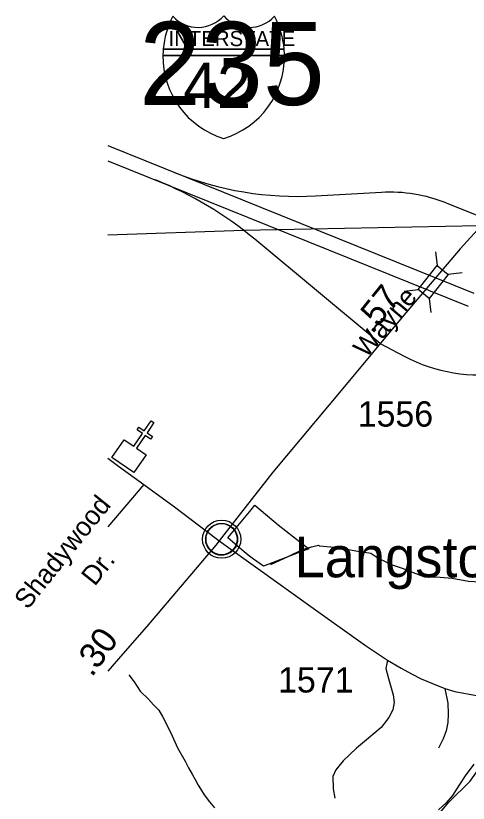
# Model space of a CAD drawing. Extents: x 2315291 to 2336543, y 597177 to 615230.
# Drawn here: x 2315291 to 2317521, y 606517 to 610401 of the extents above; entities that cross this region are included whole.
import ezdxf

# ---------------------------------------------------------------- set-up
doc = ezdxf.new("R2010")
doc.units = 0
for name, color, linetype in [('Exist Boundary Political City Limit New', 7, 'Continuous'), ('Exist Civil Demographics Community CELL', 7, 'Continuous'), ('Exist Civil Demographics Community Label', 7, 'Continuous'), ('Exist Cultural Church CELL', 7, 'Continuous'), ('Exist Hydrographic Creek Single Shore', 7, 'Continuous'), ('Exist Hydrographic Misc Water Feature', 7, 'Continuous'), ('Exist Road Non-System Type 51', 7, 'Continuous'), ('Exist Road Non-System Type 51 Label', 7, 'Continuous'), ('Exist Road Primary US Attributed', 7, 'Continuous'), ('Exist Road Primary US Shield CELL', 7, 'Continuous'), ('Exist Road Primary US Shield Number Label', 7, 'Continuous'), ('Exist Road Secondary Mileage Hundredths English Label', 7, 'Continuous'), ('Exist Road Secondary Structure Standard Bridge CELL', 7, 'Continuous'), ('Exist Road Secondary Structure Standard Bridge Number Label', 7, 'Continuous'), ('Exist Road Secondary Type 51 Attributed', 7, 'Continuous'), ('Exist Road Secondary Type 51 Label', 7, 'Continuous'), ('Exist Road Secondary Type 51 Number Label', 7, 'Continuous'), ('Exist Utilities Electrical Transmission Line', 7, 'Continuous'), ('Map Preparation Boundary City Limit Buffer Line', 7, 'Continuous')]:
    doc.layers.add(name, color=color, linetype=linetype)

msp = doc.modelspace()

# ---------------------------------------------------------------- linework, layer by layer
at = {"layer": 'Exist Boundary Political City Limit New'}
msp.add_lwpolyline([(2316682, 607751.7), (2316511.2, 607686.2), (2316462.8, 607720.3), (2316435.2, 607739.6), (2316416, 607756.2), (2316335, 607826.4), (2316450.2, 607963.4), (2316469.5, 607986.2), (2316583.5, 607889.7), (2316735, 607772), (2316682, 607751.7)], dxfattribs=at)
at = {"layer": 'Exist Civil Demographics Community CELL'}
msp.add_lwpolyline([(2316227.6, 607831.4), (2316228.6, 607837), (2316230.3, 607843.6), (2316233.3, 607850.8), (2316236.2, 607856.5), (2316239.5, 607862.3), (2316243.3, 607867.4), (2316247.2, 607871.8), (2316251.8, 607876.4), (2316257.4, 607881), (2316262.8, 607884.6), (2316267.7, 607887.5), (2316272.7, 607889.9), (2316278.2, 607892.2), (2316283.8, 607894.1), (2316288.2, 607895.2), (2316293, 607895.9), (2316297.1, 607896.7), (2316303.5, 607896.9), (2316307.9, 607896.8), (2316313.6, 607896.6), (2316318.5, 607895.8), (2316323.4, 607894.8), (2316328.4, 607893.4), (2316333.6, 607891.5), (2316340.2, 607888.6), (2316346.5, 607885.1), (2316351.6, 607881.5), (2316356.7, 607877.5), (2316360, 607874.4), (2316364.2, 607870), (2316368, 607865.3), (2316371.1, 607860.7), (2316374.2, 607855.7), (2316376.7, 607850.5), (2316378.7, 607845.5), (2316380.3, 607840.5), (2316381.6, 607835.9), (2316382.7, 607829.9), (2316383.3, 607825.2), (2316383.5, 607819.2), (2316383.4, 607813.4), (2316382.8, 607807.7), (2316381.8, 607802.2), (2316380.2, 607796.1), (2316378.3, 607790.2), (2316376, 607785.2), (2316372.9, 607779.2), (2316369.6, 607773.8), (2316366.1, 607769.1), (2316361.9, 607764.4), (2316356.6, 607759.4), (2316351.6, 607755.3), (2316346.6, 607751.9), (2316342.3, 607749.4), (2316335.5, 607746.1), (2316328.3, 607743.4), (2316322.4, 607742), (2316315.8, 607740.7), (2316311.3, 607740.2), (2316306.8, 607739.9), (2316301.3, 607739.9), (2316297, 607740.3), (2316291.3, 607741.1), (2316285.4, 607742.4), (2316280.8, 607743.7), (2316275.7, 607745.6), (2316271.1, 607747.5), (2316267.2, 607749.8), (2316260.3, 607753.9), (2316254.8, 607758.1), (2316249.9, 607762.6), (2316245.4, 607767.5), (2316242.2, 607771.4), (2316239.2, 607775.6), (2316235.1, 607782.7), (2316233.4, 607786.3), (2316231.7, 607790.3), (2316229.1, 607798.5), (2316227.6, 607805.5), (2316226.9, 607810.7), (2316226.6, 607817), (2316226.5, 607821.7), (2316227.1, 607828.2)], close=True, dxfattribs=at)
for centre, radius in [((2316305.2, 607819), 94.3), ((2316304.9, 607819.3), 76.7)]:
    msp.add_circle(centre, radius, dxfattribs=at)
at = {"layer": 'Exist Cultural Church CELL'}
msp.add_lwpolyline([(2315825, 608310), (2315871.9, 608277.7), (2315915.1, 608340.4), (2315888.8, 608358.6), (2315897.9, 608371.8), (2315924.2, 608353.6), (2315958.3, 608403.1), (2315971.5, 608394), (2315937.4, 608344.5), (2315963.7, 608326.3), (2315954.7, 608313.2), (2315928.3, 608331.3), (2315885.1, 608268.7), (2315932.5, 608235.8), (2315872.1, 608148.2), (2315764.6, 608222.3)], close=True, dxfattribs=at)
at = {"layer": 'Exist Hydrographic Creek Single Shore'}
msp.add_lwpolyline([(2317204.2, 606258.5), (2317425.2, 606522.7), (2317529.8, 606625.3), (2317606.2, 606732), (2317692.2, 606828.6), (2317781.7, 606896), (2317872.2, 606949.3), (2317905.4, 606985.5), (2317914.4, 607034.8), (2317906.3, 607550.3), (2317913.3, 607698.2), (2317970.3, 607835.1), (2318077.3, 607928.1), (2318433.3, 608145.9), (2318882.1, 608242.8), (2319139.3, 608345), (2319353.1, 608531), (2319468.2, 608666.9), (2319623.2, 609060.4), (2319840.3, 609761.6), (2319979.2, 610046.1)], dxfattribs=at)
at = {"layer": 'Exist Hydrographic Misc Water Feature'}
for points in [[(2316547.6, 607694.6), (2316633.1, 607733.3), (2316704.3, 607768.3), (2316748.6, 607780.8), (2316782.2, 607789.1), (2316788.1, 607786.9), (2316880.2, 607778), (2316966.5, 607760.9), (2317040.4, 607749.8), (2317080.7, 607724.2), (2317145.3, 607693.1), (2317195.2, 607675.4), (2317241.5, 607657.9), (2317305.7, 607632.8), (2317381.6, 607631.6), (2317441.4, 607626.2), (2317521.8, 607611.3), (2317611.8, 607607.8), (2317663.5, 607604.5), (2317715.8, 607615.3), (2317767.5, 607631.9), (2317831.4, 607640.5), (2317905.3, 607637.1), (2317939.3, 607637.6)], [(2315847.8, 607149.5), (2315874, 607115.5), (2315904.4, 607070), (2315945, 607030.2), (2315969.2, 607002.7), (2315995.6, 606975.1), (2316013.7, 606945.2), (2316054.9, 606863.6), (2316087.7, 606790.1), (2316126, 606724.4), (2316142.4, 606690.6), (2316160.5, 606660.8), (2316175, 606633.1), (2316189.2, 606605.4), (2316201.5, 606587.3), (2316219.9, 606557.8), (2316246, 606523.8), (2316270.4, 606494.2)], [(2317547.4, 606709.9), (2317506.2, 606651.3), (2317476.7, 606609.1), (2317443.5, 606554.9), (2317411.3, 606518.3), (2317373.8, 606484.2)]]:
    msp.add_lwpolyline(points, dxfattribs=at)
at = {"layer": 'Exist Road Non-System Type 51'}
msp.add_line((2315922.2, 608088.7), (2315744.5, 607880.7), dxfattribs=at)
for points in [[(2317123, 607222.5), (2317114.7, 607180.7), (2317128, 607132.4), (2317151.3, 607050.6), (2317156.3, 607013.9), (2317149.7, 606977.2), (2317129.7, 606938.9), (2317091.3, 606890.5), (2317029.6, 606837.1), (2316969.6, 606788.7), (2316904.6, 606726.2), (2316867.9, 606681.1), (2316852.9, 606647.8), (2316854.6, 606587.7), (2316862.9, 606541)], [(2317404.7, 607082.3), (2317419.7, 607010.6), (2317421.4, 606957.2), (2317419.7, 606915.5), (2317411.4, 606873), (2317396.4, 606834.6), (2317374.7, 606787.9)]]:
    msp.add_lwpolyline(points, dxfattribs=at)
at = {"layer": 'Exist Road Primary US Attributed'}
for p, q in [((2315744.5, 609760.3), (2317547.6, 609032.6)), ((2315744.5, 609686.1), (2317520.5, 608969.3)), ((2316768.1, 609512.3), (2317092.5, 609530.1)), ((2317411.1, 609477.5), (2317612.1, 609396.9)), ((2317087.3, 608784.5), (2316469.3, 609298.6)), ((2317087.3, 608784.5), (2317205.4, 608721.6))]:
    msp.add_line(p, q, dxfattribs=at)
for centre, radius, start, end in [((2316679.6, 611129.8), 1619.9, 248.0219, 273.133), ((2315289.4, 607880.2), 1845, 50.2434, 68.0219), ((2317133.2, 608784.8), 746.4, 68.1437, 93.133), ((2317575.5, 609417), 787.7, 241.9803, 279.393)]:
    msp.add_arc(centre, radius, start, end, dxfattribs=at)
at = {"layer": 'Exist Road Primary US Shield CELL'}
for p, q in [((2316017.9, 610236.3), (2316019.4, 610236.3)), ((2316613.4, 610236.3), (2316017.9, 610236.3)), ((2316019.4, 610236.3), (2316613.4, 610236.3)), ((2316019.4, 610236.3), (2316613.4, 610236.3)), ((2316016.4, 610204.8), (2316614.9, 610204.8)), ((2316614.9, 610204.8), (2316016.4, 610204.8)), ((2316016.4, 610204.8), (2316614.9, 610204.8))]:
    msp.add_line(p, q, dxfattribs=at)
for centre, radius, start, end in [((2316440.1, 610200.7), 424.1, 152.1754, 175.1644), ((2316189.1, 610511.5), 167.7, 222.2998, 318.8506), ((2316441.6, 610511.5), 167.7, 221.1494, 317.7003), ((2316190.7, 610200.7), 424.1, 4.8143, 27.8248), ((2316440.1, 610200.7), 424.1, 175.1857, 179.447), ((2316190.7, 610200.7), 424.1, 0.5526, 4.8127), ((2316440.1, 610200.7), 424.1, 179.4655, 252.7971), ((2316190.7, 610200.7), 424.1, 287.2029, 0.5405)]:
    msp.add_arc(centre, radius, start, end, dxfattribs=at)
at = {"layer": 'Exist Road Secondary Structure Standard Bridge CELL'}
for p, q in [((2317358.7, 609237.1), (2317366.7, 609168.6)), ((2317490.6, 609132.9), (2317422.1, 609124.8)), ((2317274, 609049.3), (2317205.5, 609041.2)), ((2317328.1, 609006.5), (2317336.1, 608938))]:
    msp.add_line(p, q, dxfattribs=at)
msp.add_lwpolyline([(2317422.1, 609124.8), (2317328.4, 609006.3), (2317273, 609050), (2317366.7, 609168.6)], close=True, dxfattribs=at)
at = {"layer": 'Exist Road Secondary Type 51 Attributed'}
for points in [[(2318206.6, 610154.2), (2318140.5, 610059.5), (2318076.3, 609986.8), (2317935.1, 609792), (2317731.7, 609540.9), (2317600.7, 609383.2), (2317480.8, 609251.5), (2317194.6, 608913.5), (2316902.6, 608562.2), (2316557.1, 608149.7), (2316392.1, 607937.8), (2316293.5, 607811.2)], [(2315744.5, 608218.4), (2315797.5, 608179.8), (2315922.2, 608088.7), (2316073.7, 607978.5), (2316278.1, 607822.9), (2316293.5, 607811.2)], [(2316293.5, 607811.2), (2316275.8, 607790.3), (2315934.4, 607387.6), (2315818.6, 607253.8), (2315744.5, 607168.1)], [(2316293.5, 607811.2), (2316495.8, 607665.7), (2316732.9, 607495.2), (2317014.6, 607294.2), (2317123, 607222.5), (2317190.2, 607182.1), (2317240.2, 607154.3), (2317289.1, 607131), (2317344.7, 607106.5), (2317404.7, 607082.3), (2317454.7, 607067.3), (2317561.4, 607047.3), (2317800.8, 607001.1)]]:
    msp.add_lwpolyline(points, dxfattribs=at)
at = {"layer": 'Exist Utilities Electrical Transmission Line'}
msp.add_lwpolyline([(2317575, 609365), (2316413.6, 609342), (2315744.5, 609319.6)], dxfattribs=at)
at = {"layer": 'Map Preparation Boundary City Limit Buffer Line'}
msp.add_lwpolyline([(2316682, 607751.7), (2316511.2, 607686.2), (2316462.8, 607720.3), (2316435.2, 607739.6), (2316416, 607756.2), (2316335, 607826.4), (2316450.2, 607963.4), (2316469.5, 607986.2), (2316583.5, 607889.7), (2316735, 607772), (2316682, 607751.7)], dxfattribs=at)

# ---------------------------------------------------------------- texts
at = {"layer": 'Exist Civil Demographics Community Label'}
msp.add_text('Langston', height=200, dxfattribs=at).set_placement((2316664.7, 607631.2))
at = {"layer": 'Exist Road Non-System Type 51 Label'}
for s, p in [('Shadywood', (2315349.3, 607468.2)), ('Dr.', (2315679.8, 607583.5))]:
    msp.add_text(s, height=95, rotation=51.2766, dxfattribs=at).set_placement(p)
at = {"layer": 'Exist Road Primary US Shield Number Label'}
for s, height, p in [('INTERSTATE', 75, (2316043.4, 610251.3)), ('42', 225, (2316115.4, 609945.3))]:
    msp.add_text(s, height=height, rotation=360, dxfattribs=at).set_placement(p)
at = {"layer": 'Exist Road Secondary Mileage Hundredths English Label'}
for s, rotation, p in [('.57', 51.0509, (2317047.3, 608826.9)), ('.30', 54.1365, (2315665.7, 607135))]:
    msp.add_text(s, height=125, rotation=rotation, dxfattribs=at).set_placement(p)
at = {"layer": 'Exist Road Secondary Structure Standard Bridge Number Label'}
msp.add_text('235', height=410.1, dxfattribs=at).set_placement((2315898.6, 609960.9))
at = {"layer": 'Exist Road Secondary Type 51 Label'}
msp.add_text('Wayne', height=95, rotation=49.8157, dxfattribs=at).set_placement((2317018.4, 608708.9))
at = {"layer": 'Exist Road Secondary Type 51 Number Label'}
for s, p in [('1556', (2316975.7, 608374.4)), ('1571', (2316583.2, 607062.8))]:
    msp.add_text(s, height=125, dxfattribs=at).set_placement(p)

doc.saveas('drawing.dxf')
